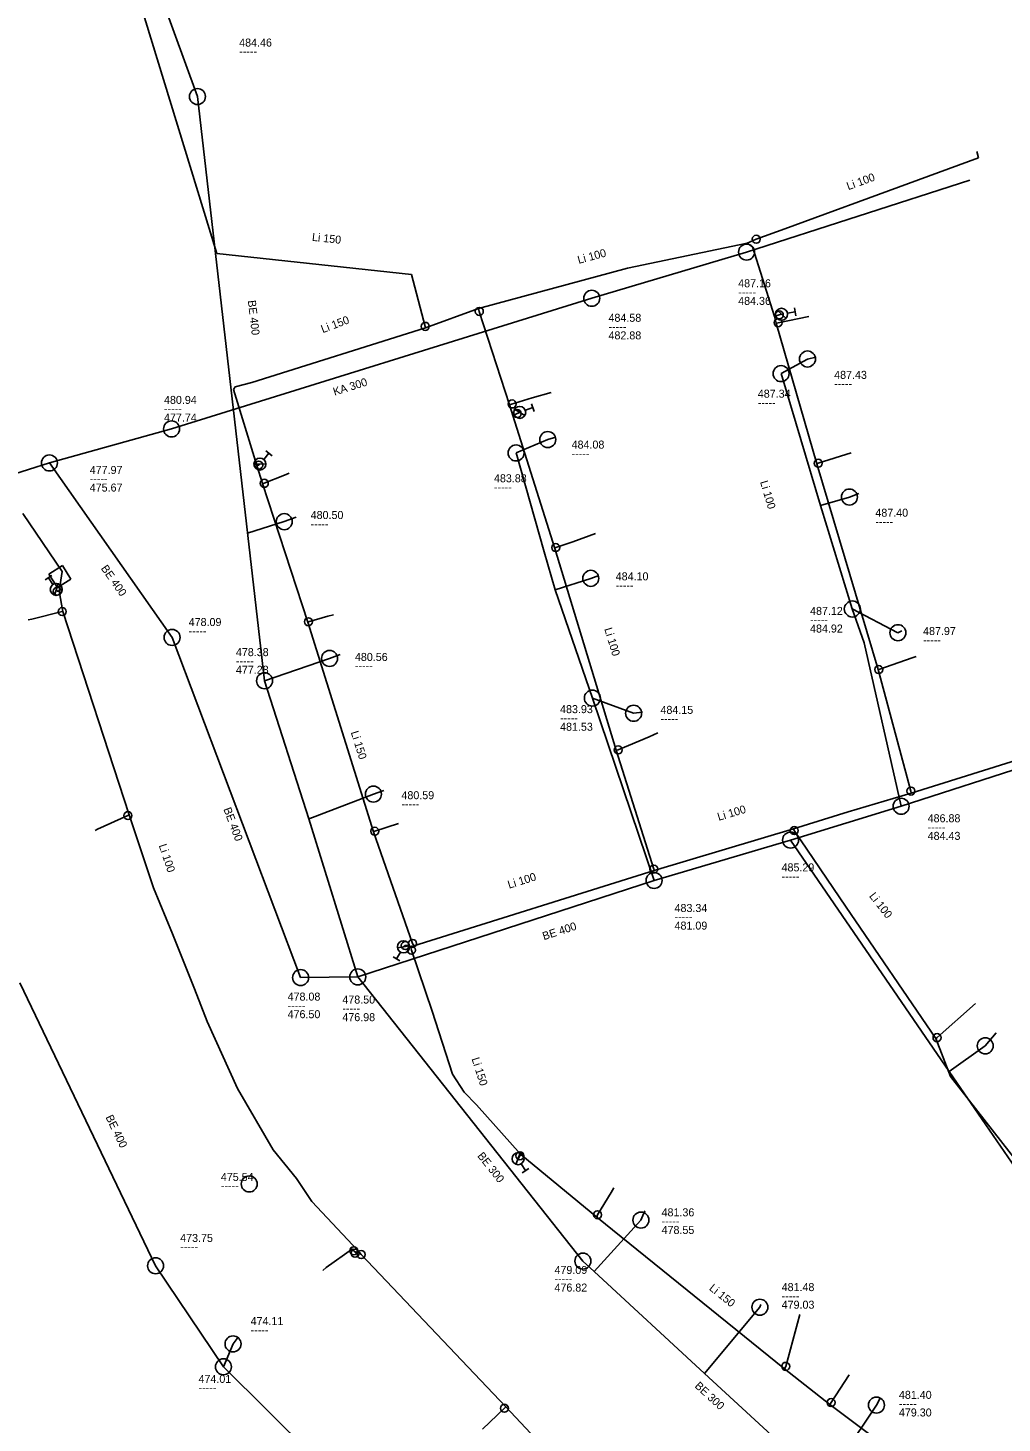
# Model space of a CAD drawing. Extents: x -685576 to -685145, y -1163436 to -1162895.
# Drawn here: x -685424.5 to -685302.8, y -1163269 to -1163094.7 of the extents above; entities that cross this region are included whole.
import ezdxf

# ---------------------------------------------------------------- set-up
doc = ezdxf.new("R2010")
doc.units = 0
doc.layers.add('Level 0', color=7, linetype='Continuous')

msp = doc.modelspace()

# ---------------------------------------------------------------- linework, layer by layer
at = {"layer": 'Level 0'}
for p, q in [((-685419.92, -1163060.93), (-685400.96, -1163122.89)), ((-685415.43, -1163069.96), (-685403.36, -1163103.27)), ((-685403.36, -1163103.27), (-685394.98, -1163176.24)), ((-685305.98, -1163110.14), (-685305.8, -1163110.92)), ((-685305.8, -1163110.92), (-685314.52, -1163114.11)), ((-685306.86, -1163113.71), (-685334.76, -1163122.69)), ((-685314.52, -1163114.11), (-685329.98, -1163119.77)), ((-685329.98, -1163119.77), (-685333.56, -1163121.08)), ((-685334.76, -1163122.69), (-685354.1, -1163128.47)), ((-685334.7, -1163121.57), (-685349.62, -1163124.69)), ((-685333.56, -1163121.08), (-685334.7, -1163121.57)), ((-685334.7, -1163121.57), (-685334.04, -1163122.04)), ((-685334.04, -1163122.04), (-685331.29, -1163130.72)), ((-685400.96, -1163122.89), (-685376.64, -1163125.5)), ((-685376.64, -1163125.5), (-685374.9, -1163131.97)), ((-685349.62, -1163124.69), (-685368.26, -1163129.74)), ((-685354.1, -1163128.47), (-685406.6, -1163144.79)), ((-685328.76, -1163129.66), (-685328.59, -1163130.65)), ((-685368.26, -1163129.74), (-685374.88, -1163132.16)), ((-685368.15, -1163130.11), (-685368.26, -1163129.74)), ((-685364.4, -1163141.76), (-685368.15, -1163130.11)), ((-685331.29, -1163130.72), (-685330.67, -1163130.55)), ((-685331.29, -1163130.72), (-685331.05, -1163131.59)), ((-685330.96, -1163129.96), (-685329.84, -1163130.96)), ((-685330.83, -1163131.52), (-685327, -1163130.75)), ((-685330.67, -1163130.55), (-685330.4, -1163130.46)), ((-685329.66, -1163130.33), (-685328.68, -1163130.16)), ((-685374.88, -1163132.16), (-685396.59, -1163139)), ((-685374.9, -1163131.97), (-685374.88, -1163132.16)), ((-685331.05, -1163131.59), (-685330.83, -1163131.52)), ((-685331.05, -1163131.59), (-685325.99, -1163149.15)), ((-685327.15, -1163136.05), (-685330.45, -1163137.88)), ((-685326.13, -1163135.81), (-685327.15, -1163136.05)), ((-685330.45, -1163137.88), (-685325.54, -1163154.34)), ((-685398.64, -1163139.54), (-685398.85, -1163139.88)), ((-685398.85, -1163139.88), (-685395.95, -1163149.35)), ((-685396.59, -1163139), (-685398.64, -1163139.54)), ((-685364.4, -1163141.76), (-685364.26, -1163141.74)), ((-685363.95, -1163143.1), (-685364.4, -1163141.76)), ((-685364.26, -1163141.74), (-685361.55, -1163140.89)), ((-685361.63, -1163141.65), (-685361.28, -1163142.59)), ((-685361.55, -1163140.89), (-685359.16, -1163140.23)), ((-685363.95, -1163143.1), (-685363.42, -1163142.86)), ((-685358.72, -1163159.71), (-685363.95, -1163143.1)), ((-685363.74, -1163142.33), (-685362.46, -1163143.12)), ((-685363.42, -1163142.86), (-685363.1, -1163142.72)), ((-685362.4, -1163142.46), (-685361.46, -1163142.12)), ((-685406.6, -1163144.79), (-685421.86, -1163149.04)), ((-685359.6, -1163146.12), (-685363.56, -1163147.79)), ((-685358.61, -1163145.83), (-685359.6, -1163146.12)), ((-685395.08, -1163148.6), (-685394.44, -1163147.83)), ((-685394.82, -1163147.51), (-685394.05, -1163148.15)), ((-685363.56, -1163147.79), (-685360.04, -1163160.15)), ((-685325.81, -1163149.08), (-685321.71, -1163147.77)), ((-685421.86, -1163149.04), (-685427.1, -1163150.7)), ((-685406.53, -1163170.83), (-685421.86, -1163149.04)), ((-685396.31, -1163149.15), (-685394.81, -1163149.2)), ((-685395.95, -1163149.35), (-685395.71, -1163149.31)), ((-685395.95, -1163149.35), (-685395.25, -1163151.62)), ((-685395.71, -1163149.31), (-685395.56, -1163149.17)), ((-685395.01, -1163151.58), (-685392.48, -1163150.56)), ((-685392.48, -1163150.56), (-685391.9, -1163150.32)), ((-685325.99, -1163149.15), (-685325.81, -1163149.08)), ((-685325.99, -1163149.15), (-685318.32, -1163174.84)), ((-685395.25, -1163151.62), (-685395.01, -1163151.58)), ((-685395.25, -1163151.62), (-685389.58, -1163168.91)), ((-685321.91, -1163153.29), (-685325.54, -1163154.34)), ((-685320.73, -1163152.84), (-685321.91, -1163153.29)), ((-685420.25, -1163162.58), (-685425.17, -1163155.33)), ((-685391.04, -1163155.81), (-685392.52, -1163156.37)), ((-685325.54, -1163154.34), (-685321.55, -1163167.28)), ((-685392.52, -1163156.37), (-685397.1, -1163157.8)), ((-685358.6, -1163159.6), (-685356.45, -1163158.89)), ((-685356.45, -1163158.89), (-685353.62, -1163157.83)), ((-685360.04, -1163160.15), (-685358.69, -1163164.9)), ((-685358.72, -1163159.71), (-685358.6, -1163159.6)), ((-685351.04, -1163184.9), (-685358.72, -1163159.71)), ((-685420.24, -1163161.85), (-685421.93, -1163162.92)), ((-685420.65, -1163165.07), (-685420.25, -1163162.58)), ((-685419.17, -1163163.54), (-685420.24, -1163161.85)), ((-685422.38, -1163163.65), (-685421.55, -1163163.09)), ((-685421.41, -1163164.2), (-685421.96, -1163163.37)), ((-685421.93, -1163162.92), (-685420.86, -1163164.61)), ((-685421.24, -1163165.54), (-685420.76, -1163164.12)), ((-685420.86, -1163164.61), (-685419.17, -1163163.54)), ((-685354.22, -1163163.45), (-685358.69, -1163164.9)), ((-685353.2, -1163163.08), (-685354.22, -1163163.45)), ((-685420.88, -1163165.07), (-685421, -1163164.83)), ((-685420.65, -1163165.07), (-685420.88, -1163165.07)), ((-685420.19, -1163167.58), (-685420.65, -1163165.07)), ((-685358.69, -1163164.9), (-685354.03, -1163178.41)), ((-685420.26, -1163167.61), (-685424.07, -1163168.53)), ((-685420.19, -1163167.58), (-685420.26, -1163167.61)), ((-685411.88, -1163192.98), (-685420.19, -1163167.58)), ((-685387.08, -1163168.19), (-685386.38, -1163167.99)), ((-685321.55, -1163167.28), (-685320.09, -1163171.52)), ((-685315.85, -1163170.24), (-685321.55, -1163167.28)), ((-685424.07, -1163168.53), (-685424.53, -1163168.64)), ((-685389.58, -1163168.91), (-685389.5, -1163168.87)), ((-685389.58, -1163168.91), (-685381.37, -1163195.13)), ((-685389.5, -1163168.87), (-685387.08, -1163168.19)), ((-685390.47, -1163213.33), (-685406.53, -1163170.83)), ((-685315.38, -1163170.02), (-685315.85, -1163170.24)), ((-685385.53, -1163172.98), (-685386.86, -1163173.46)), ((-685320.09, -1163171.52), (-685315.45, -1163191.93)), ((-685314.06, -1163173.39), (-685313.57, -1163173.23)), ((-685386.86, -1163173.46), (-685394.98, -1163176.24)), ((-685318.32, -1163174.84), (-685318.25, -1163174.84)), ((-685318.32, -1163174.84), (-685314.24, -1163190.02)), ((-685318.25, -1163174.84), (-685314.06, -1163173.39)), ((-685394.98, -1163176.24), (-685389.46, -1163193.48)), ((-685354.03, -1163178.41), (-685346.32, -1163201.19)), ((-685348.87, -1163180.31), (-685354.03, -1163178.41)), ((-685347.77, -1163180.15), (-685348.87, -1163180.31)), ((-685273.88, -1163178.51), (-685315.45, -1163191.93)), ((-685350.8, -1163184.89), (-685346.94, -1163183.25)), ((-685346.94, -1163183.25), (-685345.84, -1163182.74)), ((-685289.58, -1163182.54), (-685314.18, -1163190.28)), ((-685351.04, -1163184.9), (-685350.8, -1163184.89)), ((-685346.35, -1163199.78), (-685351.04, -1163184.9)), ((-685381.38, -1163190.4), (-685389.55, -1163193.52)), ((-685380.09, -1163189.97), (-685381.38, -1163190.4)), ((-685314.18, -1163190.28), (-685322.05, -1163192.61)), ((-685314.24, -1163190.02), (-685314.18, -1163190.28)), ((-685315.45, -1163191.93), (-685329.26, -1163196.15)), ((-685412.05, -1163193.09), (-685415.85, -1163194.8)), ((-685411.88, -1163192.98), (-685412.05, -1163193.09)), ((-685408.85, -1163202.11), (-685411.88, -1163192.98)), ((-685389.46, -1163193.48), (-685389.45, -1163193.49)), ((-685389.45, -1163193.49), (-685383.34, -1163213.24)), ((-685381.21, -1163195.04), (-685378.26, -1163194.07)), ((-685322.05, -1163192.61), (-685328.91, -1163194.76)), ((-685415.85, -1163194.8), (-685416.16, -1163194.95)), ((-685381.37, -1163195.13), (-685381.21, -1163195.04)), ((-685381.37, -1163195.13), (-685376.48, -1163209.06)), ((-685328.91, -1163194.76), (-685346.31, -1163199.95)), ((-685328.8, -1163194.96), (-685328.91, -1163194.76)), ((-685322.31, -1163204.53), (-685328.8, -1163194.96)), ((-685329.26, -1163196.15), (-685346.32, -1163201.19)), ((-685309.45, -1163225.05), (-685329.26, -1163196.15)), ((-685346.31, -1163199.95), (-685376.33, -1163209.36)), ((-685346.31, -1163199.95), (-685346.35, -1163199.78)), ((-685406.47, -1163207.84), (-685408.85, -1163202.11)), ((-685346.32, -1163201.19), (-685383.34, -1163213.24)), ((-685311.11, -1163220.95), (-685322.31, -1163204.53)), ((-685403.73, -1163214.71), (-685406.47, -1163207.84)), ((-685376.88, -1163209.37), (-685378.36, -1163209.59)), ((-685377.4, -1163209.32), (-685377.62, -1163209.48)), ((-685377.17, -1163209.28), (-685377.4, -1163209.32)), ((-685376.72, -1163209.55), (-685377.17, -1163209.28)), ((-685376.33, -1163209.36), (-685376.72, -1163209.55)), ((-685376.72, -1163209.55), (-685376.64, -1163209.9)), ((-685376.48, -1163209.06), (-685376.33, -1163209.36)), ((-685378.06, -1163211.25), (-685378.93, -1163210.75)), ((-685377.99, -1163210.13), (-685378.49, -1163211)), ((-685376.64, -1163209.9), (-685374.03, -1163217.52)), ((-685383.34, -1163213.24), (-685390.47, -1163213.33)), ((-685383.34, -1163213.24), (-685355.21, -1163248.74)), ((-685425.56, -1163214), (-685408.59, -1163249.33)), ((-685402.13, -1163218.81), (-685403.73, -1163214.71)), ((-685310.97, -1163220.83), (-685306.17, -1163216.55)), ((-685374.03, -1163217.52), (-685371.51, -1163225.37)), ((-685398.38, -1163227.18), (-685402.13, -1163218.81)), ((-685303.56, -1163220.24), (-685304.94, -1163221.85)), ((-685311.11, -1163220.95), (-685310.97, -1163220.83)), ((-685309.3, -1163225.68), (-685311.11, -1163220.95)), ((-685304.94, -1163221.85), (-685309.45, -1163225.05)), ((-685371.51, -1163225.37), (-685370.03, -1163227.64)), ((-685297.86, -1163241.96), (-685309.45, -1163225.05)), ((-685393.89, -1163234.85), (-685398.38, -1163227.18)), ((-685300.66, -1163236.72), (-685309.3, -1163225.68)), ((-685370.03, -1163227.64), (-685368.52, -1163229.24)), ((-685368.52, -1163229.24), (-685362.98, -1163235.41)), ((-685391.01, -1163238.41), (-685393.89, -1163234.85)), ((-685363.05, -1163235.25), (-685363.57, -1163236.66)), ((-685363.08, -1163235.58), (-685363.31, -1163235.95)), ((-685362.98, -1163235.41), (-685363.08, -1163235.58)), ((-685362.98, -1163235.41), (-685353.47, -1163243.25)), ((-685362.91, -1163236.59), (-685362.39, -1163237.44)), ((-685361.96, -1163237.17), (-685362.81, -1163237.7)), ((-685389.06, -1163241.28), (-685391.01, -1163238.41)), ((-685353.38, -1163242.96), (-685351.69, -1163240.16)), ((-685351.69, -1163240.16), (-685351.34, -1163239.61)), ((-685383.31, -1163247.4), (-685389.06, -1163241.28)), ((-685347.49, -1163242.45), (-685347.96, -1163243.62)), ((-685347.96, -1163243.62), (-685353.8, -1163250.04)), ((-685353.47, -1163243.25), (-685353.38, -1163242.96)), ((-685353.47, -1163243.25), (-685330.04, -1163262.19)), ((-685384.01, -1163247.19), (-685387.27, -1163249.55)), ((-685383.83, -1163247.45), (-685384.01, -1163247.19)), ((-685383.57, -1163247.66), (-685383.83, -1163247.45)), ((-685383.67, -1163247.77), (-685383.57, -1163247.66)), ((-685383.57, -1163247.66), (-685383.31, -1163247.4)), ((-685383.31, -1163247.4), (-685382.91, -1163247.92)), ((-685364.83, -1163266.94), (-685382.91, -1163247.92)), ((-685408.59, -1163249.33), (-685400.12, -1163261.95)), ((-685387.27, -1163249.55), (-685387.72, -1163249.9)), ((-685355.21, -1163248.74), (-685353.8, -1163250.04)), ((-685353.8, -1163250.04), (-685340, -1163262.77)), ((-685333.1, -1163254.5), (-685340, -1163262.77)), ((-685332.97, -1163254.17), (-685333.1, -1163254.5)), ((-685329.86, -1163261.89), (-685328.11, -1163255.43)), ((-685398.28, -1163258.25), (-685398.92, -1163259.09)), ((-685398.92, -1163259.09), (-685400.12, -1163261.95)), ((-685400.12, -1163261.95), (-685382.02, -1163279.88)), ((-685330.04, -1163262.19), (-685329.86, -1163261.89)), ((-685340, -1163262.77), (-685328.96, -1163272.95)), ((-685330.04, -1163262.19), (-685324.37, -1163266.65)), ((-685324.21, -1163266.41), (-685321.93, -1163262.95)), ((-685365.02, -1163267.13), (-685367.75, -1163269.74)), ((-685364.83, -1163266.94), (-685365.02, -1163267.13)), ((-685364.79, -1163266.94), (-685364.83, -1163266.94)), ((-685346.37, -1163286.69), (-685364.83, -1163266.94)), ((-685318.54, -1163266.73), (-685324.77, -1163276.07)), ((-685324.37, -1163266.65), (-685324.21, -1163266.41)), ((-685324.37, -1163266.65), (-685313.39, -1163274.86)), ((-685318.13, -1163265.94), (-685318.54, -1163266.73))]:
    msp.add_line(p, q, dxfattribs=at)
for centre, radius in [((-685403.36, -1163103.27), 1), ((-685333.56, -1163121.08), 0.5), ((-685334.76, -1163122.69), 1), ((-685354.1, -1163128.47), 1), ((-685368.15, -1163130.11), 0.5), ((-685330.83, -1163131.52), 0.5), ((-685330.67, -1163130.55), 0.5), ((-685330.4, -1163130.46), 0.75), ((-685374.9, -1163131.97), 0.5), ((-685327.15, -1163136.05), 1), ((-685330.45, -1163137.88), 1), ((-685364.05, -1163141.67), 0.5), ((-685363.42, -1163142.86), 0.5), ((-685363.1, -1163142.72), 0.75), ((-685406.6, -1163144.79), 1), ((-685359.6, -1163146.12), 1), ((-685363.56, -1163147.79), 1), ((-685421.86, -1163149.04), 1), ((-685395.56, -1163149.17), 0.75), ((-685395.71, -1163149.31), 0.5), ((-685325.81, -1163149.08), 0.5), ((-685395.01, -1163151.58), 0.5), ((-685321.91, -1163153.29), 1), ((-685392.52, -1163156.37), 1), ((-685358.6, -1163159.6), 0.5), ((-685354.22, -1163163.45), 1), ((-685421, -1163164.83), 0.75), ((-685420.88, -1163165.07), 0.5), ((-685420.26, -1163167.61), 0.5), ((-685321.55, -1163167.28), 1), ((-685389.5, -1163168.87), 0.5), ((-685315.85, -1163170.24), 1), ((-685406.53, -1163170.83), 1), ((-685386.86, -1163173.46), 1), ((-685318.25, -1163174.84), 0.5), ((-685394.98, -1163176.24), 1), ((-685354.03, -1163178.41), 1), ((-685348.87, -1163180.31), 1), ((-685350.8, -1163184.89), 0.5), ((-685381.38, -1163190.4), 1), ((-685314.24, -1163190.02), 0.5), ((-685315.45, -1163191.93), 1), ((-685412.05, -1163193.09), 0.5), ((-685381.21, -1163195.04), 0.5), ((-685329.26, -1163196.15), 1), ((-685328.8, -1163194.96), 0.5), ((-685346.35, -1163199.78), 0.5), ((-685346.32, -1163201.19), 1), ((-685377.62, -1163209.48), 0.75), ((-685377.4, -1163209.32), 0.5), ((-685376.64, -1163209.9), 0.5), ((-685376.48, -1163209.06), 0.5), ((-685390.47, -1163213.33), 1), ((-685383.34, -1163213.24), 1), ((-685310.97, -1163220.83), 0.5), ((-685304.94, -1163221.85), 1), ((-685363.31, -1163235.95), 0.75), ((-685363.08, -1163235.58), 0.5), ((-685396.89, -1163239.11), 1), ((-685353.38, -1163242.96), 0.5), ((-685347.96, -1163243.62), 1), ((-685383.83, -1163247.45), 0.5), ((-685383.67, -1163247.77), 0.5), ((-685382.91, -1163247.92), 0.5), ((-685355.21, -1163248.74), 1), ((-685408.59, -1163249.33), 1), ((-685333.1, -1163254.5), 1), ((-685398.92, -1163259.09), 1), ((-685400.12, -1163261.95), 1), ((-685329.86, -1163261.89), 0.5), ((-685365.02, -1163267.13), 0.5), ((-685324.21, -1163266.41), 0.5), ((-685318.54, -1163266.73), 1)]:
    msp.add_circle(centre, radius, dxfattribs=at)

# ---------------------------------------------------------------- texts
for s, p in [('484.46', (-685398.15, -1163097.02)), ('-----', (-685398.15, -1163098.12)), ('487.16', (-685335.81, -1163127.09)), ('-----', (-685335.81, -1163128.19)), ('484.36', (-685335.81, -1163129.29)), ('484.58', (-685352.01, -1163131.4)), ('482.88', (-685352.01, -1163133.6)), ('-----', (-685352.01, -1163132.5)), ('487.43', (-685323.82, -1163138.53)), ('487.34', (-685333.36, -1163140.88)), ('-----', (-685323.82, -1163139.63)), ('480.94', (-685407.54, -1163141.66)), ('-----', (-685333.36, -1163141.98)), ('477.74', (-685407.54, -1163143.86)), ('-----', (-685407.54, -1163142.76)), ('484.08', (-685356.62, -1163147.24)), ('-----', (-685356.62, -1163148.34)), ('477.97', (-685416.82, -1163150.41)), ('483.88', (-685366.32, -1163151.45)), ('475.67', (-685416.82, -1163152.61)), ('-----', (-685416.82, -1163151.51)), ('-----', (-685366.32, -1163152.55)), ('480.50', (-685389.22, -1163156.04)), ('487.40', (-685318.67, -1163155.75)), ('-----', (-685389.22, -1163157.14)), ('-----', (-685318.67, -1163156.85)), ('484.10', (-685351.11, -1163163.7)), ('-----', (-685351.11, -1163164.8)), ('487.12', (-685326.83, -1163168.02)), ('478.09', (-685404.46, -1163169.41)), ('484.92', (-685326.83, -1163170.22)), ('-----', (-685326.83, -1163169.12)), ('487.97', (-685312.71, -1163170.53)), ('-----', (-685404.46, -1163170.51)), ('-----', (-685312.71, -1163171.63)), ('478.38', (-685398.56, -1163173.17)), ('480.56', (-685383.69, -1163173.77)), ('477.28', (-685398.56, -1163175.37)), ('-----', (-685398.56, -1163174.27)), ('-----', (-685383.69, -1163174.87)), ('483.93', (-685358.06, -1163180.29)), ('484.15', (-685345.52, -1163180.38)), ('481.53', (-685358.06, -1163182.49)), ('-----', (-685358.06, -1163181.39)), ('-----', (-685345.52, -1163181.48)), ('480.59', (-685377.88, -1163191.04)), ('-----', (-685377.88, -1163192.14)), ('486.88', (-685312.14, -1163193.92)), ('484.43', (-685312.14, -1163196.12)), ('-----', (-685312.14, -1163195.02)), ('485.29', (-685330.39, -1163200.06)), ('-----', (-685330.39, -1163201.16)), ('483.34', (-685343.76, -1163205.13)), ('481.09', (-685343.76, -1163207.33)), ('-----', (-685343.76, -1163206.23)), ('478.08', (-685392.1, -1163216.2)), ('478.50', (-685385.26, -1163216.57)), ('476.50', (-685392.1, -1163218.4)), ('-----', (-685392.1, -1163217.3)), ('476.98', (-685385.26, -1163218.77)), ('-----', (-685385.26, -1163217.67)), ('475.54', (-685400.44, -1163238.73)), ('-----', (-685400.44, -1163239.83)), ('481.36', (-685345.38, -1163243.15)), ('478.55', (-685345.38, -1163245.35)), ('-----', (-685345.38, -1163244.25)), ('473.75', (-685405.52, -1163246.35)), ('-----', (-685405.52, -1163247.45)), ('479.09', (-685358.76, -1163250.35)), ('476.82', (-685358.76, -1163252.55)), ('-----', (-685358.76, -1163251.45)), ('481.48', (-685330.38, -1163252.49)), ('-----', (-685330.38, -1163253.59)), ('479.03', (-685330.38, -1163254.69)), ('474.11', (-685396.72, -1163256.73)), ('-----', (-685396.72, -1163257.83)), ('474.01', (-685403.23, -1163263.96)), ('-----', (-685403.23, -1163265.06)), ('481.40', (-685315.73, -1163265.95)), ('479.30', (-685315.73, -1163268.15)), ('-----', (-685315.73, -1163267.05))]:
    msp.add_text(s, height=1, dxfattribs=at).set_placement(p)
for s, rotation, p in [('Li 100', 20.108, (-685322.05, -1163114.97)), ('Li 150', 353.88, (-685389.09, -1163121.28)), ('Li 100', 15.159, (-685355.73, -1163124.17)), ('BE 400', 276.551, (-685397.07, -1163128.76)), ('Li 150', 20.59, (-685387.71, -1163132.83)), ('KA 300', 17.268, (-685386.24, -1163140.64)), ('Li 100', 286.624, (-685333.09, -1163151.4)), ('BE 400', 305.128, (-685415.47, -1163162.21)), ('Li 100', 286.956, (-685352.55, -1163169.77)), ('Li 150', 287.386, (-685384.22, -1163182.68)), ('BE 400', 290.701, (-685400.14, -1163192.28)), ('Li 100', 16.609, (-685338.24, -1163193.75)), ('Li 100', 288.36, (-685408.21, -1163196.82)), ('Li 100', 17.404, (-685364.43, -1163202.23)), ('Li 100', 308.047, (-685319.5, -1163203.16)), ('BE 400', 18.03, (-685360.08, -1163208.66)), ('Li 150', 287.798, (-685369.13, -1163223.47)), ('BE 400', 295.657, (-685414.87, -1163230.76)), ('BE 300', 308.393, (-685368.45, -1163235.62)), ('Li 150', 321.049, (-685339.52, -1163252.27)), ('BE 300', 317.314, (-685341.32, -1163264.44))]:
    msp.add_text(s, height=1, rotation=rotation, dxfattribs=at).set_placement(p)

doc.saveas('drawing.dxf')
